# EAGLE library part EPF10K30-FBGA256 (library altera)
EPF10K30 FLEX 10K family
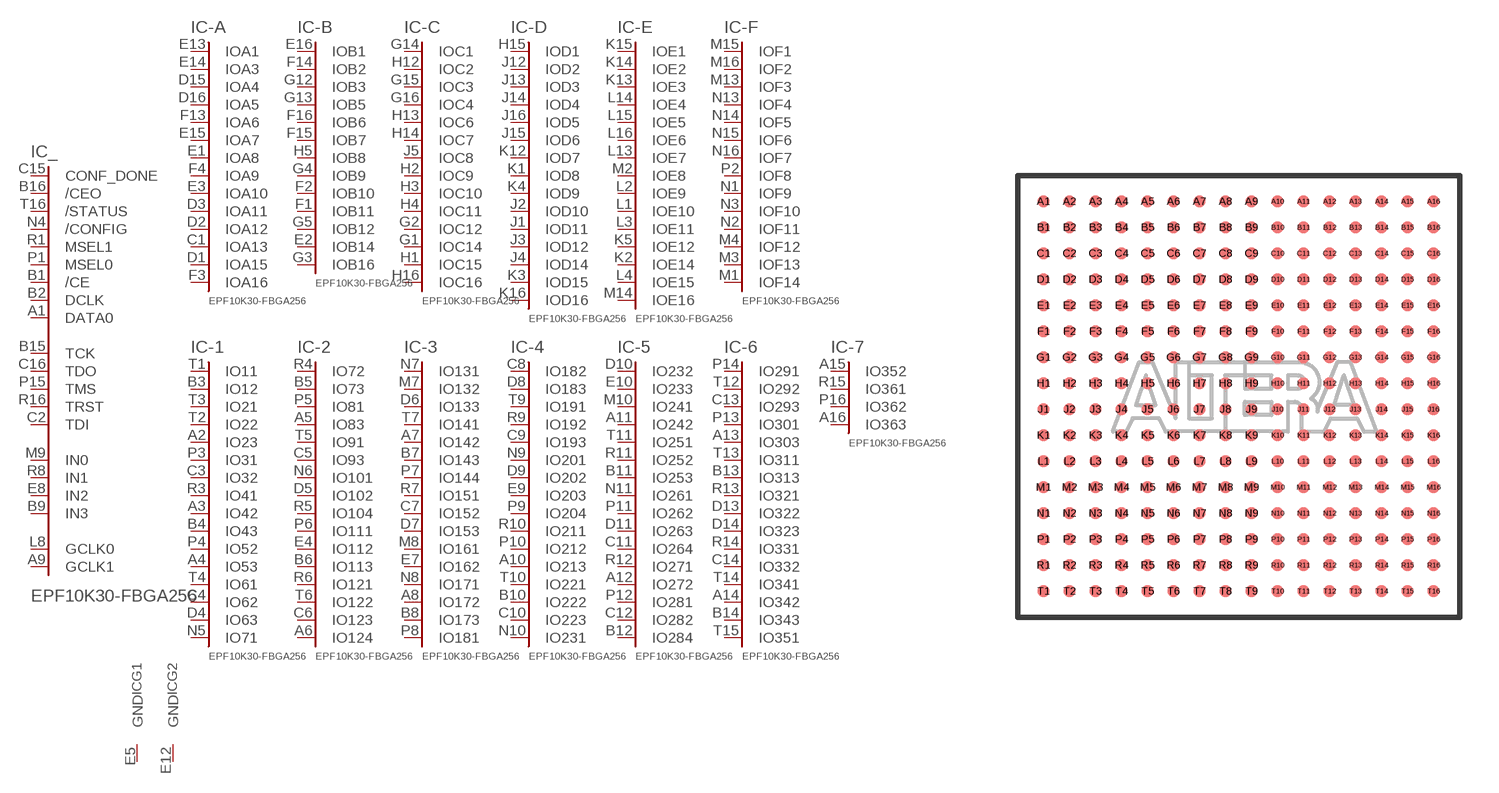
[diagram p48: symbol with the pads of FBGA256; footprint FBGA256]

Designator prefix IC; gates _=100R240C -A=A16-30B -B=B16-30B -C=C16-30B -D=D16-30B -E=E16-30B -F=F14-30B -1=71-30B -2=124-30B -3=181-30B -4=231-30B -5=284-30B -6=351-30B -7=363-30B G1=GND G2=GND G3=GND G4=GND G5=GND G6=GND G7=GND G8=GND G9=GND G10=GND G11=GND G12=GND G13=GND G14=GND G15=GND G16=GND G17=GND G18=GND V1=VCCINT V2=VCCINT V3=VCCINT V4=VCCINT V5=VCCINT V6=VCCINT V7=VCCINT V8=VCCINT V9=VCCINT V10=VCCINT V11=VCCINT V12=VCCINT V13=VCCINT V14=VCCINT V15=VCCINT V16=VCCINT V17=VCCINT V18=VCCINT VO1=VCCIO VO2=VCCIO VO3=VCCIO VO4=VCCIO VO5=VCCIO VO6=VCCIO VO7=VCCIO VO8=VCCIO VO9=VCCIO VO10=VCCIO VO11=VCCIO VO12=VCCIO VO13=VCCIO VO14=VCCIO VO15=VCCIO

## EPF10K30-FBGA256 (MPN: EPF10K30EFC256-3N; OC_FARNELL: 1549394; OC_NEWARK: 51R8977)  [FBGA256]
A1  _:DATA0  in
A2  -1:IO23
A3  -1:IO42
A4  -1:IO53
A5  -2:IO83
A6  -2:IO124
A7  -3:IO142
A8  -3:IO172
A9  _:GCLK1  in
A10  -4:IO213
A11  -5:IO242
A12  -5:IO272
A13  -6:IO303
A14  -6:IO342
A15  -7:IO352
A16  -7:IO363
B1  _:/CE  in
B2  _:DCLK  in
B3  -1:IO12
B4  -1:IO43
B5  -2:IO73
B6  -2:IO113
B7  -3:IO143
B8  -3:IO173
B9  _:IN3  in
B10  -4:IO222
B11  -5:IO253
B12  -5:IO284
B13  -6:IO313
B14  -6:IO343
B15  _:TCK
B16  _:/CEO  in
C1  -A:IOA13
C2  _:TDI
C3  -1:IO32
C4  -1:IO62
C5  -2:IO93
C6  -2:IO123
C7  -3:IO152
C8  -4:IO182
C9  -4:IO193
C10  -4:IO223
C11  -5:IO264
C12  -5:IO282
C13  -6:IO293
C14  -6:IO332
C15  _:CONF_DONE  in
C16  _:TDO
D1  -A:IOA15
D2  -A:IOA12
D3  -A:IOA11
D4  -1:IO63
D5  -2:IO102
D6  -3:IO133
D7  -3:IO153
D8  -4:IO183
D9  -4:IO202
D10  -5:IO232
D11  -5:IO263
D12  VO1:VCCIO  pwr
D13  -6:IO322
D14  -6:IO323
D15  -A:IOA4
D16  -A:IOA5
E1  -A:IOA8
E2  -B:IOB14
E3  -A:IOA10
E4  -2:IO112
E5  G1:GND  pwr
E6  VO2:VCCIO  pwr
E7  -3:IO162
E8  _:IN2  in
E9  -4:IO203
E10  -5:IO233
E11  V1:VCC  pwr
E12  G2:GND  pwr
E13  -A:IOA1
E14  -A:IOA3
E15  -A:IOA7
E16  -B:IOB1
F1  -B:IOB11
F2  -B:IOB10
F3  -A:IOA16
F4  -A:IOA9
F5  V2:VCC  pwr
F6  G3:GND  pwr
F7  V3:VCC  pwr
F8  VO3:VCCIO  pwr
F9  V4:VCC  pwr
F10  VO4:VCCIO  pwr
F11  G4:GND  pwr
F12  V5:VCC  pwr
F13  -A:IOA6
F14  -B:IOB2
F15  -B:IOB7
F16  -B:IOB6
G1  -C:IOC14
G2  -C:IOC12
G3  -B:IOB16
G4  -B:IOB9
G5  -B:IOB12
G6  VO5:VCCIO  pwr
G7  G5:GND  pwr
G8  VO6:VCCIO  pwr
G9  G6:GND  pwr
G10  G7:GND  pwr
G11  VO7:VCCIO  pwr
G12  -B:IOB3
G13  -B:IOB5
G14  -C:IOC1
G15  -C:IOC3
G16  -C:IOC4
H1  -C:IOC15
H2  -C:IOC9
H3  -C:IOC10
H4  -C:IOC11
H5  -B:IOB8
H6  V6:VCC  pwr
H7  V7:VCC  pwr
H8  G8:GND  pwr
H9  G9:GND  pwr
H10  V8:VCC  pwr
H11  VO8:VCCIO  pwr
H12  -C:IOC2
H13  -C:IOC6
H14  -C:IOC7
H15  -D:IOD1
H16  -C:IOC16
J1  -D:IOD11
J2  -D:IOD10
J3  -D:IOD12
J4  -D:IOD14
J5  -C:IOC8
J6  VO9:VCCIO  pwr
J7  V9:VCC  pwr
J8  G10:GND  pwr
J9  G11:GND  pwr
J10  V10:VCC  pwr
J11  V11:VCC  pwr
J12  -D:IOD2
J13  -D:IOD3
J14  -D:IOD4
J15  -D:IOD6
J16  -D:IOD5
K1  -D:IOD8
K2  -E:IOE14
K3  -D:IOD15
K4  -D:IOD9
K5  -E:IOE12
K6  VO10:VCCIO  pwr
K7  G12:GND  pwr
K8  VO11:VCCIO  pwr
K9  V12:VCC  pwr
K10  G13:GND  pwr
K11  VO12:VCCIO  pwr
K12  -D:IOD7
K13  -E:IOE3
K14  -E:IOE2
K15  -E:IOE1
K16  -D:IOD16
L1  -E:IOE10
L2  -E:IOE9
L3  -E:IOE11
L4  -E:IOE15
L5  V13:VCC  pwr
L6  G14:GND  pwr
L7  V14:VCC  pwr
L8  _:GCLK0  in
L9  V15:VCC  pwr
L10  VO13:VCCIO  pwr
L11  G15:GND  pwr
L12  V16:VCC  pwr
L13  -E:IOE7
L14  -E:IOE4
L15  -E:IOE5
L16  -E:IOE6
M1  -F:IOF14
M2  -E:IOE8
M3  -F:IOF13
M4  -F:IOF12
M5  G16:GND  pwr
M6  VO14:VCCIO  pwr
M7  -3:IO132
M8  -3:IO161
M9  _:IN0  in
M10  -5:IO241
M11  V17:VCC  pwr
M12  G17:GND  pwr
M13  -F:IOF3
M14  -E:IOE16
M15  -F:IOF1
M16  -F:IOF2
N1  -F:IOF9
N2  -F:IOF11
N3  -F:IOF10
N4  _:/CONFIG  in
N5  -1:IO71
N6  -2:IO101
N7  -3:IO131
N8  -3:IO171
N9  -4:IO201
N10  -4:IO231
N11  -5:IO261
N12  VO15:VCCIO  pwr
N13  -F:IOF4
N14  -F:IOF5
N15  -F:IOF6
N16  -F:IOF7
P1  _:MSEL0  in
P2  -F:IOF8
P3  -1:IO31
P4  -1:IO52
P5  -2:IO81
P6  -2:IO111
P7  -3:IO144
P8  -3:IO181
P9  -4:IO204
P10  -4:IO212
P11  -5:IO262
P12  -5:IO281
P13  -6:IO301
P14  -6:IO291
P15  _:TMS
P16  -7:IO362
R1  _:MSEL1  in
R2  V18:VCC  pwr
R3  -1:IO41
R4  -2:IO72
R5  -2:IO104
R6  -2:IO121
R7  -3:IO151
R8  _:IN1  in
R9  -4:IO192
R10  -4:IO211
R11  -5:IO252
R12  -5:IO271
R13  -6:IO321
R14  -6:IO331
R15  -7:IO361
R16  _:TRST
T1  -1:IO11
T2  -1:IO22
T3  -1:IO21
T4  -1:IO61
T5  -2:IO91
T6  -2:IO122
T7  -3:IO141
T8  G18:GND  pwr
T9  -4:IO191
T10  -4:IO221
T11  -5:IO251
T12  -6:IO292
T13  -6:IO311
T14  -6:IO341
T15  -6:IO351
T16  _:/STATUS  in

## Footprint FBGA256 (pad centres in mm)
Fine Ball Grid Array
smd 0.45 x 0.45: A1 -7.5,7.5; A2 -6.5,7.5; A3 -5.5,7.5; A4 -4.5,7.5; A5 -3.5,7.5; A6 -2.5,7.5; A7 -1.5,7.5; A8 -0.5,7.5; A9 0.5,7.5; A10 1.5,7.5; A11 2.5,7.5; A12 3.5,7.5; A13 4.5,7.5; A14 5.5,7.5; A15 6.5,7.5; A16 7.5,7.5; B1 -7.5,6.5; B2 -6.5,6.5; B3 -5.5,6.5; B4 -4.5,6.5; B5 -3.5,6.5; B6 -2.5,6.5; B7 -1.5,6.5; B8 -0.5,6.5; B9 0.5,6.5; B10 1.5,6.5; B11 2.5,6.5; B12 3.5,6.5; B13 4.5,6.5; B14 5.5,6.5; B15 6.5,6.5; B16 7.5,6.5; C1 -7.5,5.5; C2 -6.5,5.5; C3 -5.5,5.5; C4 -4.5,5.5; C5 -3.5,5.5; C6 -2.5,5.5; C7 -1.5,5.5; C8 -0.5,5.5; C9 0.5,5.5; C10 1.5,5.5; C11 2.5,5.5; C12 3.5,5.5; C13 4.5,5.5; C14 5.5,5.5; C15 6.5,5.5; C16 7.5,5.5; D1 -7.5,4.5; D2 -6.5,4.5; D3 -5.5,4.5; D4 -4.5,4.5; D5 -3.5,4.5; D6 -2.5,4.5; D7 -1.5,4.5; D8 -0.5,4.5; D9 0.5,4.5; D10 1.5,4.5; D11 2.5,4.5; D12 3.5,4.5; D13 4.5,4.5; D14 5.5,4.5; D15 6.5,4.5; D16 7.5,4.5; E1 -7.5,3.5; E2 -6.5,3.5; E3 -5.5,3.5; E4 -4.5,3.5; E5 -3.5,3.5; E6 -2.5,3.5; E7 -1.5,3.5; E8 -0.5,3.5; E9 0.5,3.5; E10 1.5,3.5; E11 2.5,3.5; E12 3.5,3.5; E13 4.5,3.5; E14 5.5,3.5; E15 6.5,3.5; E16 7.5,3.5; F1 -7.5,2.5; F2 -6.5,2.5; F3 -5.5,2.5; F4 -4.5,2.5; F5 -3.5,2.5; F6 -2.5,2.5; F7 -1.5,2.5; F8 -0.5,2.5; F9 0.5,2.5; F10 1.5,2.5; F11 2.5,2.5; F12 3.5,2.5; F13 4.5,2.5; F14 5.5,2.5; F15 6.5,2.5; F16 7.5,2.5; G1 -7.5,1.5; G2 -6.5,1.5; G3 -5.5,1.5; G4 -4.5,1.5; G5 -3.5,1.5; G6 -2.5,1.5; G7 -1.5,1.5; G8 -0.5,1.5; G9 0.5,1.5; G10 1.5,1.5; G11 2.5,1.5; G12 3.5,1.5; G13 4.5,1.5; G14 5.5,1.5; G15 6.5,1.5; G16 7.5,1.5; H1 -7.5,0.5; H2 -6.5,0.5; H3 -5.5,0.5; H4 -4.5,0.5; H5 -3.5,0.5; H6 -2.5,0.5; H7 -1.5,0.5; H8 -0.5,0.5; H9 0.5,0.5; H10 1.5,0.5; H11 2.5,0.5; H12 3.5,0.5; H13 4.5,0.5; H14 5.5,0.5; H15 6.5,0.5; H16 7.5,0.5; J1 -7.5,-0.5; J2 -6.5,-0.5; J3 -5.5,-0.5; J4 -4.5,-0.5; J5 -3.5,-0.5; J6 -2.5,-0.5; J7 -1.5,-0.5; J8 -0.5,-0.5; J9 0.5,-0.5; J10 1.5,-0.5; J11 2.5,-0.5; J12 3.5,-0.5; J13 4.5,-0.5; J14 5.5,-0.5; J15 6.5,-0.5; J16 7.5,-0.5; K1 -7.5,-1.5; K2 -6.5,-1.5; K3 -5.5,-1.5; K4 -4.5,-1.5; K5 -3.5,-1.5; K6 -2.5,-1.5; K7 -1.5,-1.5; K8 -0.5,-1.5; K9 0.5,-1.5; K10 1.5,-1.5; K11 2.5,-1.5; K12 3.5,-1.5; K13 4.5,-1.5; K14 5.5,-1.5; K15 6.5,-1.5; K16 7.5,-1.5; L1 -7.5,-2.5; L2 -6.5,-2.5; L3 -5.5,-2.5; L4 -4.5,-2.5; L5 -3.5,-2.5; L6 -2.5,-2.5; L7 -1.5,-2.5; L8 -0.5,-2.5; L9 0.5,-2.5; L10 1.5,-2.5; L11 2.5,-2.5; L12 3.5,-2.5; L13 4.5,-2.5; L14 5.5,-2.5; L15 6.5,-2.5; L16 7.5,-2.5; M1 -7.5,-3.5; M2 -6.5,-3.5; M3 -5.5,-3.5; M4 -4.5,-3.5; M5 -3.5,-3.5; M6 -2.5,-3.5; M7 -1.5,-3.5; M8 -0.5,-3.5; M9 0.5,-3.5; M10 1.5,-3.5; M11 2.5,-3.5; M12 3.5,-3.5; M13 4.5,-3.5; M14 5.5,-3.5; M15 6.5,-3.5; M16 7.5,-3.5; N1 -7.5,-4.5; N2 -6.5,-4.5; N3 -5.5,-4.5; N4 -4.5,-4.5; N5 -3.5,-4.5; N6 -2.5,-4.5; N7 -1.5,-4.5; N8 -0.5,-4.5; N9 0.5,-4.5; N10 1.5,-4.5; N11 2.5,-4.5; N12 3.5,-4.5; N13 4.5,-4.5; N14 5.5,-4.5; N15 6.5,-4.5; N16 7.5,-4.5; P1 -7.5,-5.5; P2 -6.5,-5.5; P3 -5.5,-5.5; P4 -4.5,-5.5; P5 -3.5,-5.5; P6 -2.5,-5.5; P7 -1.5,-5.5; P8 -0.5,-5.5; P9 0.5,-5.5; P10 1.5,-5.5; P11 2.5,-5.5; P12 3.5,-5.5; P13 4.5,-5.5; P14 5.5,-5.5; P15 6.5,-5.5; P16 7.5,-5.5; R1 -7.5,-6.5; R2 -6.5,-6.5; R3 -5.5,-6.5; R4 -4.5,-6.5; R5 -3.5,-6.5; R6 -2.5,-6.5; R7 -1.5,-6.5; R8 -0.5,-6.5; R9 0.5,-6.5; R10 1.5,-6.5; R11 2.5,-6.5; R12 3.5,-6.5; R13 4.5,-6.5; R14 5.5,-6.5; R15 6.5,-6.5; R16 7.5,-6.5; T1 -7.5,-7.5; T2 -6.5,-7.5; T3 -5.5,-7.5; T4 -4.5,-7.5; T5 -3.5,-7.5; T6 -2.5,-7.5; T7 -1.5,-7.5; T8 -0.5,-7.5; T9 0.5,-7.5; T10 1.5,-7.5; T11 2.5,-7.5; T12 3.5,-7.5; T13 4.5,-7.5; T14 5.5,-7.5; T15 6.5,-7.5; T16 7.5,-7.5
